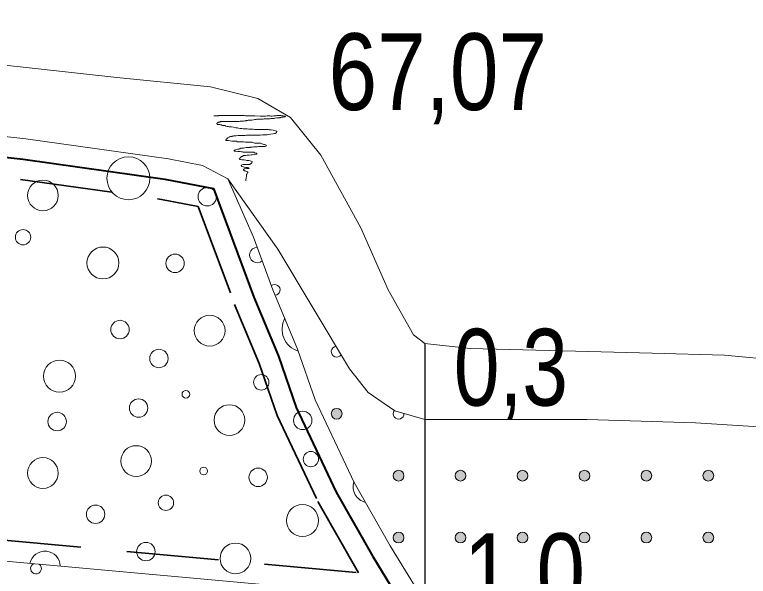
# Model space of a CAD drawing. Extents: x 640104 to 640970, y 6442278 to 6442689.
# Drawn here: x 640398.4 to 640427.06, y 6442382.35 to 6442404.3 of the extents above; entities that cross this region are included whole.
import ezdxf
from ezdxf.enums import TextEntityAlignment as Align

# ---------------------------------------------------------------- set-up
doc = ezdxf.new("R2010")
doc.units = 0
doc.header["$LTSCALE"] = 1.2
doc.linetypes.add('MEDIUM_DASHED', pattern=[4.5, 3, -1.5])
for name, color, linetype, lineweight in [('31', 7, 'Continuous', 13), ('32', 7, 'Continuous', 25), ('35', 7, 'Continuous', 35), ('40', 7, 'Continuous', 13), ('41', 7, 'Continuous', 13), ('44', 7, 'Continuous', 13), ('45', 7, 'Continuous', 13)]:
    doc.layers.add(name, color=color, linetype=linetype, lineweight=lineweight)

msp = doc.modelspace()

# ---------------------------------------------------------------- hatches: boundary and pattern name
at = {"layer": '45'}
for points in [[(640411.183, 6442388.703, 1), (640410.763, 6442388.703, 1)], [(640413.603, 6442386.283, 1), (640413.183, 6442386.283, 1)], [(640416.023, 6442386.283, 1), (640415.603, 6442386.283, 1)], [(640418.443, 6442386.283, 1), (640418.023, 6442386.283, 1)], [(640420.863, 6442386.283, 1), (640420.443, 6442386.283, 1)], [(640423.283, 6442386.283, 1), (640422.863, 6442386.283, 1)], [(640425.703, 6442386.283, 1), (640425.283, 6442386.283, 1)], [(640413.603, 6442383.863, 1), (640413.183, 6442383.863, 1)], [(640416.023, 6442383.863, 1), (640415.603, 6442383.863, 1)], [(640418.443, 6442383.863, 1), (640418.023, 6442383.863, 1)], [(640420.863, 6442383.863, 1), (640420.443, 6442383.863, 1)], [(640423.283, 6442383.863, 1), (640422.863, 6442383.863, 1)], [(640425.703, 6442383.863, 1), (640425.283, 6442383.863, 1)]]:
    msp.add_hatch(color=256, dxfattribs=at).paths.add_polyline_path(points)

# ---------------------------------------------------------------- linework, layer by layer
at = {"layer": '31'}
for points in [[(640139.08, 6442423.82), (640151.96, 6442423.75), (640173.66, 6442421.26), (640213.16, 6442416.61), (640233.94, 6442414.53), (640242.79, 6442413.66), (640295.17, 6442389.83), (640328.15, 6442387.74), (640358.78, 6442385.66), (640377.96, 6442384.87), (640391.41, 6442383.72), (640397.31, 6442383.01), (640414.42, 6442381.45)], [(640364.92, 6442406.94), (640373.37, 6442405.52), (640381.69, 6442404.79), (640389.76, 6442403.83), (640396, 6442402.55), (640402.39, 6442401.84), (640406.05, 6442401.48), (640407.9, 6442401.02), (640409.17, 6442400.28), (640410.36, 6442398.81), (640411.92, 6442395.97), (640412.99, 6442393.55), (640413.98, 6442391.78), (640414.42, 6442391.45), (640416.19, 6442391.25), (640420.81, 6442391.14), (640423.3, 6442391.07), (640426.12, 6442390.99), (640428.35, 6442390.78)], [(640370.83, 6442403.34), (640375.09, 6442402.49), (640381.81, 6442401.59), (640387.22, 6442400.99), (640394.72, 6442399.9), (640398.83, 6442399.44), (640404.4, 6442398.66), (640405.74, 6442398.4), (640406.72, 6442397.88), (640408.68, 6442395.14), (640411.47, 6442390.46), (640412.2, 6442389.53), (640413.25, 6442388.81), (640414.42, 6442388.48), (640420.75, 6442388.48), (640424.99, 6442388.35), (640432.03, 6442387.9)], [(640406.72, 6442397.88), (640407.72, 6442395.6), (640408.48, 6442393.55), (640409.45, 6442391.23), (640410.13, 6442389.25), (640411.66, 6442386.01), (640413.07, 6442383.54), (640414.37, 6442381.42), (640415.13, 6442380.9), (640419.37, 6442380.37), (640424.37, 6442380.25), (640433.96, 6442379.98), (640441.04, 6442380.03), (640448.6, 6442379.6), (640453.66, 6442379.25), (640461.37, 6442378.83)]]:
    msp.add_lwpolyline(points, dxfattribs=at)
at = {"layer": '32'}
msp.add_line((640414.42, 6442391.45), (640414.42, 6442344.45), dxfattribs=at)
at = {"layer": '35', "linetype": 'MEDIUM_DASHED'}
for points in [[(640153.52, 6442424.38), (640173.75, 6442422.06), (640213.24, 6442417.41), (640234.02, 6442415.33), (640243, 6442414.44), (640295.36, 6442390.62), (640328.2, 6442388.54), (640358.82, 6442386.46), (640378.01, 6442385.67), (640391.49, 6442384.52), (640397.4, 6442383.81), (640411.83, 6442382.49)], [(640310.73, 6442417.89), (640314.69, 6442416.45), (640322.35, 6442414.15), (640330.95, 6442411.93), (640341.43, 6442408.86), (640348.57, 6442407.03), (640357.22, 6442404.61), (640362.94, 6442403.12), (640370.53, 6442401.77), (640374.82, 6442400.91), (640381.61, 6442400), (640387.01, 6442399.4), (640394.51, 6442398.31), (640398.63, 6442397.86), (640404.13, 6442397.08), (640405.57, 6442396.8)], [(640405.57, 6442396.8), (640406.99, 6442392.97), (640407.95, 6442390.66), (640408.65, 6442388.64), (640410.24, 6442385.27), (640411.83, 6442382.49)]]:
    msp.add_lwpolyline(points, dxfattribs=at)
at = {"layer": '35', "lineweight": 40}
for points in [[(640311.07, 6442418.61), (640314.94, 6442417.21), (640322.56, 6442414.92), (640331.16, 6442412.7), (640341.64, 6442409.63), (640348.78, 6442407.8), (640357.43, 6442405.38), (640363.12, 6442403.9), (640370.68, 6442402.55), (640374.95, 6442401.7), (640381.71, 6442400.8), (640387.11, 6442400.2), (640394.62, 6442399.11), (640398.73, 6442398.65), (640404.26, 6442397.87), (640406.16, 6442397.5)], [(640406.16, 6442397.5), (640407.74, 6442393.26), (640408.7, 6442390.95), (640409.39, 6442388.95), (640410.95, 6442385.64), (640412.39, 6442383.13), (640413.77, 6442380.86), (640414.84, 6442380.13), (640419.31, 6442379.57), (640424.35, 6442379.45), (640433.96, 6442379.18), (640441.02, 6442379.23), (640448.55, 6442378.8), (640453.61, 6442378.45), (640461.31, 6442378.03)]]:
    msp.add_lwpolyline(points, dxfattribs=at)
at = {"layer": '40'}
for points in [[(640406.17, 6442400.35), (640406.21, 6442400.35), (640406.28, 6442400.35), (640406.36, 6442400.35), (640406.37, 6442400.36), (640406.44, 6442400.36), (640406.55, 6442400.36), (640406.76, 6442400.36), (640406.88, 6442400.36), (640406.91, 6442400.36), (640406.93, 6442400.36), (640406.98, 6442400.36), (640407.04, 6442400.36), (640407.11, 6442400.36), (640407.16, 6442400.36), (640407.2, 6442400.36), (640407.26, 6442400.36), (640407.31, 6442400.36), (640407.36, 6442400.36), (640407.41, 6442400.35), (640407.44, 6442400.35), (640407.49, 6442400.35), (640407.56, 6442400.35), (640407.78, 6442400.34), (640407.99, 6442400.33), (640408.05, 6442400.33), (640408.09, 6442400.33), (640408.12, 6442400.33), (640408.15, 6442400.33), (640408.2, 6442400.33), (640408.26, 6442400.34), (640408.29, 6442400.34), (640408.32, 6442400.34), (640408.33, 6442400.34), (640408.36, 6442400.34), (640408.4, 6442400.33), (640408.43, 6442400.33), (640408.46, 6442400.33), (640408.52, 6442400.34), (640408.56, 6442400.34), (640408.61, 6442400.35), (640408.64, 6442400.36), (640408.68, 6442400.36), (640408.71, 6442400.36), (640408.74, 6442400.36), (640408.77, 6442400.36), (640408.8, 6442400.36), (640408.82, 6442400.35), (640408.85, 6442400.34), (640408.88, 6442400.34)], [(640408.88, 6442400.34), (640408.91, 6442400.33), (640408.93, 6442400.33), (640408.96, 6442400.33), (640408.98, 6442400.32), (640408.96, 6442400.31), (640408.97, 6442400.32), (640408.95, 6442400.31), (640408.92, 6442400.3), (640408.88, 6442400.29), (640408.85, 6442400.29), (640408.82, 6442400.29), (640408.8, 6442400.28), (640408.77, 6442400.28), (640408.76, 6442400.27), (640408.72, 6442400.27), (640408.67, 6442400.26), (640408.64, 6442400.26), (640408.56, 6442400.25), (640408.53, 6442400.24), (640408.51, 6442400.24), (640408.48, 6442400.24), (640408.44, 6442400.24), (640408.42, 6442400.24), (640408.38, 6442400.23), (640408.36, 6442400.23), (640408.28, 6442400.23), (640408.24, 6442400.23), (640408.2, 6442400.23), (640408.14, 6442400.23), (640408.1, 6442400.22), (640408.07, 6442400.22), (640408.03, 6442400.21), (640407.99, 6442400.21), (640407.88, 6442400.21), (640407.85, 6442400.21), (640407.83, 6442400.2), (640407.78, 6442400.2), (640407.72, 6442400.19), (640407.66, 6442400.18), (640407.62, 6442400.18), (640407.56, 6442400.17), (640407.52, 6442400.17), (640407.49, 6442400.16), (640407.45, 6442400.16), (640407.44, 6442400.15), (640407.41, 6442400.15), (640407.37, 6442400.15), (640407.34, 6442400.14), (640407.32, 6442400.14), (640407.23, 6442400.13), (640407.2, 6442400.13)], [(640407.2, 6442400.13), (640407.17, 6442400.12), (640407.13, 6442400.12), (640407.11, 6442400.12), (640407.08, 6442400.12), (640407.06, 6442400.12), (640407.03, 6442400.12), (640407, 6442400.12), (640406.96, 6442400.12), (640406.92, 6442400.12), (640406.89, 6442400.12), (640406.85, 6442400.12), (640406.83, 6442400.12), (640406.8, 6442400.12), (640406.78, 6442400.12), (640406.75, 6442400.12), (640406.72, 6442400.12), (640406.67, 6442400.12), (640406.64, 6442400.12), (640406.62, 6442400.12), (640406.58, 6442400.12), (640406.56, 6442400.12), (640406.52, 6442400.12), (640406.5, 6442400.12), (640406.47, 6442400.12), (640406.44, 6442400.12), (640406.41, 6442400.1), (640406.38, 6442400.1), (640406.36, 6442400.09), (640406.34, 6442400.08), (640406.32, 6442400.08), (640406.31, 6442400.06), (640406.3, 6442400.04), (640406.31, 6442400.01), (640406.37, 6442400), (640406.41, 6442400), (640406.44, 6442399.99), (640406.47, 6442399.99), (640406.49, 6442399.98), (640406.51, 6442399.97), (640406.55, 6442399.97), (640406.58, 6442399.96), (640406.6, 6442399.96), (640406.65, 6442399.94), (640406.7, 6442399.93), (640406.75, 6442399.93), (640406.78, 6442399.92), (640406.81, 6442399.92), (640406.87, 6442399.91), (640406.94, 6442399.9)], [(640406.94, 6442399.9), (640407.04, 6442399.88), (640407.1, 6442399.87), (640407.14, 6442399.86), (640407.2, 6442399.85), (640407.27, 6442399.85), (640407.32, 6442399.84), (640407.36, 6442399.84), (640407.39, 6442399.83), (640407.44, 6442399.83), (640407.48, 6442399.83), (640407.54, 6442399.82), (640407.6, 6442399.82), (640407.64, 6442399.82), (640407.71, 6442399.82), (640407.76, 6442399.81), (640407.8, 6442399.81), (640407.83, 6442399.81), (640407.88, 6442399.81), (640407.92, 6442399.81), (640407.98, 6442399.81), (640408.04, 6442399.81), (640408.1, 6442399.81), (640408.14, 6442399.81), (640408.2, 6442399.81), (640408.22, 6442399.81), (640408.26, 6442399.81), (640408.3, 6442399.81), (640408.34, 6442399.8), (640408.38, 6442399.8), (640408.41, 6442399.8), (640408.5, 6442399.79), (640408.54, 6442399.77), (640408.58, 6442399.76), (640408.61, 6442399.75), (640408.64, 6442399.74), (640408.64, 6442399.72), (640408.63, 6442399.69), (640408.61, 6442399.68), (640408.6, 6442399.68), (640408.58, 6442399.66), (640408.55, 6442399.65), (640408.49, 6442399.64), (640408.4, 6442399.63), (640408.31, 6442399.61), (640408.26, 6442399.6), (640408.2, 6442399.6), (640408.14, 6442399.6), (640408.08, 6442399.6), (640407.99, 6442399.59), (640407.86, 6442399.59), (640407.75, 6442399.59)], [(640407.75, 6442399.59), (640407.69, 6442399.59), (640407.64, 6442399.59), (640407.59, 6442399.59), (640407.55, 6442399.59), (640407.51, 6442399.59), (640407.45, 6442399.59), (640407.4, 6442399.58), (640407.28, 6442399.58), (640407.22, 6442399.58), (640407.19, 6442399.57), (640407.13, 6442399.57), (640407.05, 6442399.56), (640406.96, 6442399.56), (640406.93, 6442399.55), (640406.89, 6442399.55), (640406.88, 6442399.54), (640406.85, 6442399.53), (640406.83, 6442399.53), (640406.8, 6442399.52), (640406.78, 6442399.52), (640406.76, 6442399.5), (640406.72, 6442399.48), (640406.7, 6442399.46), (640406.69, 6442399.44), (640406.67, 6442399.44), (640406.66, 6442399.42), (640406.64, 6442399.4), (640406.64, 6442399.39), (640406.65, 6442399.38), (640406.68, 6442399.38), (640406.72, 6442399.38), (640406.75, 6442399.38), (640406.82, 6442399.37), (640406.88, 6442399.36), (640406.94, 6442399.36), (640407.02, 6442399.35), (640407.06, 6442399.35), (640407.1, 6442399.33), (640407.14, 6442399.33), (640407.25, 6442399.33), (640407.34, 6442399.33), (640407.41, 6442399.32), (640407.48, 6442399.32), (640407.58, 6442399.31), (640407.68, 6442399.31), (640407.76, 6442399.28), (640407.81, 6442399.28), (640407.88, 6442399.28), (640407.93, 6442399.28)], [(640407.93, 6442399.28), (640407.96, 6442399.28), (640408, 6442399.27), (640408.05, 6442399.25), (640408.1, 6442399.24), (640408.13, 6442399.23), (640408.16, 6442399.22), (640408.2, 6442399.21), (640408.22, 6442399.2), (640408.23, 6442399.17), (640408.21, 6442399.16), (640408.2, 6442399.16), (640408.17, 6442399.15), (640408.09, 6442399.14), (640408.05, 6442399.14), (640408.03, 6442399.14), (640407.98, 6442399.14), (640407.92, 6442399.14), (640407.87, 6442399.13), (640407.84, 6442399.13), (640407.8, 6442399.13), (640407.72, 6442399.13), (640407.67, 6442399.12), (640407.64, 6442399.12), (640407.6, 6442399.12), (640407.58, 6442399.11), (640407.54, 6442399.11), (640407.48, 6442399.11), (640407.44, 6442399.1), (640407.38, 6442399.09), (640407.34, 6442399.08), (640407.32, 6442399.08), (640407.28, 6442399.08), (640407.26, 6442399.08), (640407.22, 6442399.08), (640407.21, 6442399.06), (640407.17, 6442399.05), (640407.16, 6442399.04), (640407.13, 6442399.04), (640407.1, 6442399.04), (640407.06, 6442399.03), (640407.02, 6442399.02), (640406.99, 6442399), (640406.97, 6442398.99), (640406.97, 6442398.96), (640407, 6442398.96), (640407.04, 6442398.96), (640407.11, 6442398.95), (640407.16, 6442398.95), (640407.2, 6442398.95), (640407.26, 6442398.94), (640407.3, 6442398.94)], [(640407.3, 6442398.94), (640407.32, 6442398.93), (640407.34, 6442398.93), (640407.38, 6442398.93), (640407.43, 6442398.93), (640407.45, 6442398.93), (640407.52, 6442398.92), (640407.58, 6442398.92), (640407.6, 6442398.92), (640407.64, 6442398.92), (640407.66, 6442398.92), (640407.7, 6442398.92), (640407.74, 6442398.92), (640407.77, 6442398.9), (640407.8, 6442398.89), (640407.84, 6442398.88), (640407.86, 6442398.88), (640407.86, 6442398.84), (640407.78, 6442398.83), (640407.68, 6442398.82), (640407.64, 6442398.82), (640407.56, 6442398.81), (640407.52, 6442398.81), (640407.48, 6442398.81), (640407.43, 6442398.8), (640407.38, 6442398.8), (640407.33, 6442398.79), (640407.28, 6442398.76), (640407.26, 6442398.75), (640407.23, 6442398.73), (640407.21, 6442398.72), (640407.2, 6442398.7), (640407.19, 6442398.68), (640407.17, 6442398.65), (640407.19, 6442398.64), (640407.22, 6442398.64), (640407.27, 6442398.62), (640407.36, 6442398.62), (640407.43, 6442398.61), (640407.47, 6442398.6), (640407.5, 6442398.6), (640407.55, 6442398.6), (640407.6, 6442398.59), (640407.67, 6442398.56), (640407.67, 6442398.53), (640407.66, 6442398.51), (640407.65, 6442398.49), (640407.6, 6442398.45), (640407.58, 6442398.44), (640407.54, 6442398.44), (640407.48, 6442398.44), (640407.43, 6442398.44), (640407.38, 6442398.44), (640407.32, 6442398.44), (640407.27, 6442398.43), (640407.26, 6442398.4), (640407.25, 6442398.39), (640407.26, 6442398.37), (640407.28, 6442398.36), (640407.36, 6442398.34), (640407.42, 6442398.33), (640407.45, 6442398.32), (640407.49, 6442398.32), (640407.53, 6442398.31), (640407.56, 6442398.29), (640407.54, 6442398.28), (640407.5, 6442398.28), (640407.45, 6442398.28), (640407.39, 6442398.27), (640407.36, 6442398.27), (640407.34, 6442398.26), (640407.34, 6442398.23), (640407.36, 6442398.21), (640407.37, 6442398.2), (640407.4, 6442398.19), (640407.43, 6442398.18), (640407.47, 6442398.17), (640407.5, 6442398.16), (640407.51, 6442398.13), (640407.49, 6442398.12), (640407.48, 6442398.09), (640407.47, 6442398.07), (640407.45, 6442398.05), (640407.45, 6442398.02), (640407.45, 6442397.99), (640407.45, 6442397.96), (640407.44, 6442397.94), (640407.44, 6442397.91), (640407.44, 6442397.89), (640407.43, 6442397.86), (640407.42, 6442397.84), (640407.42, 6442397.8), (640407.42, 6442397.8), (640407.42, 6442397.82)]]:
    msp.add_lwpolyline(points, dxfattribs=at)
at = {"layer": '41'}
for centre, radius in [((640402.839, 6442397.903), 0.838), ((640399.5, 6442397.232), 0.6), ((640405.918, 6442397.181), 0.36), ((640398.723, 6442395.6), 0.3), ((640401.845, 6442394.594), 0.624), ((640404.664, 6442394.579), 0.36), ((640406.013, 6442391.949), 0.6), ((640402.511, 6442391.993), 0.36), ((640404.03, 6442390.861), 0.36), ((640400.149, 6442390.169), 0.624), ((640408.029, 6442389.93), 0.3), ((640405.083, 6442389.465), 0.15), ((640403.238, 6442388.924), 0.36), ((640406.787, 6442388.454), 0.6), ((640400.056, 6442388.398), 0.36), ((640409.649, 6442388.44), 0.36), ((640403.142, 6442386.854), 0.6), ((640409.967, 6442386.929), 0.3), ((640399.5, 6442386.386), 0.6), ((640405.779, 6442386.464), 0.15), ((640407.908, 6442386.217), 0.36), ((640404.306, 6442385.222), 0.3), ((640401.557, 6442384.776), 0.36), ((640409.641, 6442384.528), 0.624), ((640403.521, 6442383.314), 0.36), ((640407.021, 6442383.047), 0.6)]:
    msp.add_circle(centre, radius, dxfattribs=at)
for centre, radius, start, end in [((640407.873, 6442394.901), 0.3, 90.4945, 310.1891), ((640409.731, 6442392.005), 0.889, 151.3869, 253.5067), ((640412.243, 6442385.848), 0.624, 162.0392, 257.1535), ((640399.578, 6442382.735), 0.6, 1.0716, 168.2902)]:
    msp.add_arc(centre, radius, start, end, dxfattribs=at)
at = {"layer": '44'}
msp.add_arc((640399.229, 6442382.655), 0.21, 116.3486, 53.0132, dxfattribs=at)
at = {"layer": '45'}
for centre in [(640410.973, 6442388.703), (640413.393, 6442386.283), (640415.813, 6442386.283), (640418.233, 6442386.283), (640420.653, 6442386.283), (640423.073, 6442386.283), (640425.493, 6442386.283), (640413.393, 6442383.863), (640415.813, 6442383.863), (640418.233, 6442383.863), (640420.653, 6442383.863), (640423.073, 6442383.863), (640425.493, 6442383.863)]:
    msp.add_circle(centre, 0.21, dxfattribs=at)
for centre, start, end in [((640408.553, 6442393.543), 275.4057, 128.0467), ((640410.973, 6442391.123), 95.6612, 326.0183), ((640413.393, 6442388.703), 144.0512, 2.2399)]:
    msp.add_arc(centre, 0.21, start, end, dxfattribs=at)

# ---------------------------------------------------------------- texts
at = {"layer": '32'}
for s, width, p in [('67,07', 0.85, (640414.925, 6442400.57)), ('0,3', 0.8, (640417.78, 6442389.02)), ('1,0', 0.85, (640418.305, 6442381.03))]:
    msp.add_text(s, height=3, dxfattribs=dict(at, width=width)).set_placement(p, align=Align.CENTER)

doc.saveas('drawing.dxf')
